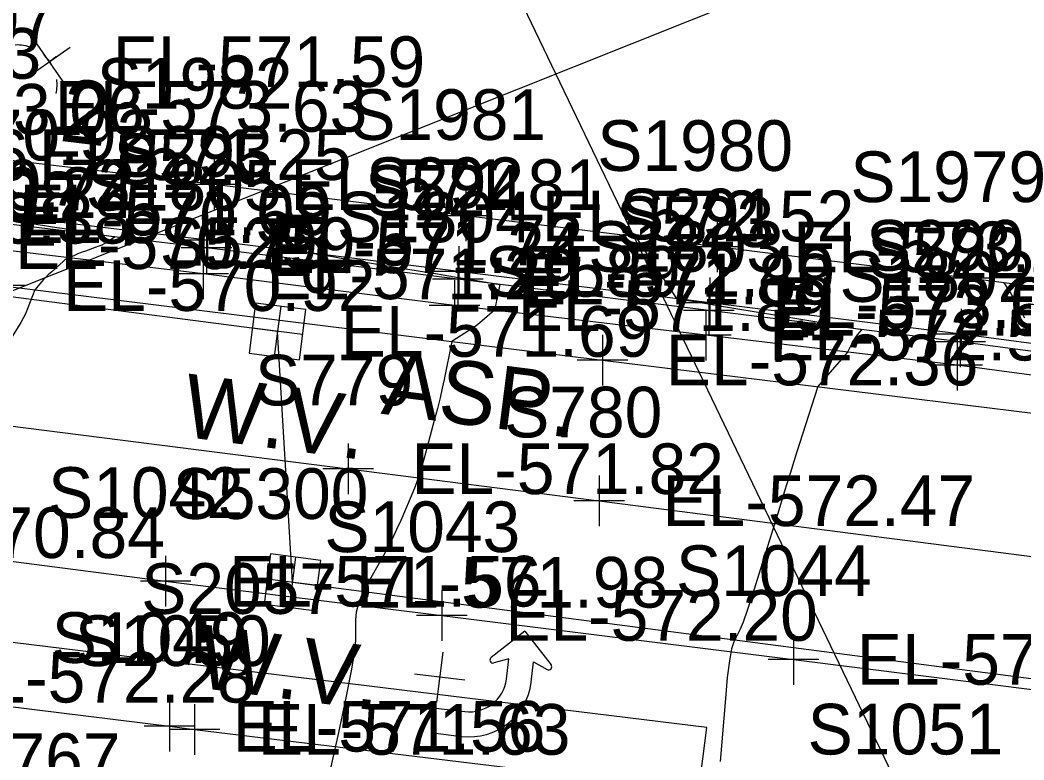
# Model space of a CAD drawing. Extents: x 1724534 to 1727318, y 657156 to 660047.
# Drawn here: x 1725826.2 to 1725905.5, y 658565.7 to 658624.1 of the extents above; entities that cross this region are included whole.
import ezdxf

# ---------------------------------------------------------------- set-up
doc = ezdxf.new("R2010")
doc.units = 0
for name, color, linetype in [('SURVEY - CENTERLINE - Preliminary Text', 7, 'Continuous'), ('SURVEY - CONTOURS - Intermediate with optional Text', 7, 'Continuous'), ('SURVEY - DRAINAGE - Area Shapes', 7, 'Continuous'), ('SURVEY - DRAINAGE - Storm Sewer', 7, 'Continuous'), ('SURVEY - DTM - Breaklines', 7, 'Continuous'), ('SURVEY - DTM - Breaklines - Points - Elevations', 7, 'Continuous'), ('SURVEY - DTM - Breaklines - Points - Locators', 7, 'Continuous'), ('SURVEY - DTM - Breaklines - Points - Numbers', 7, 'Continuous'), ('SURVEY - ROADSIDE BARRIERS - Points - Elevations', 7, 'Continuous'), ('SURVEY - ROADSIDE BARRIERS - Points - Numbers', 7, 'Continuous'), ('SURVEY - TRAFFIC CONTROL - Pavement Marking - Points - Elevations', 7, 'Continuous'), ('SURVEY - TRAFFIC CONTROL - Pavement Marking - Points - Locators', 7, 'Continuous'), ('SURVEY - TRAFFIC CONTROL - Pavement Marking - Points - Numbers', 7, 'Continuous'), ('SURVEY - TRAFFIC CONTROL - Pavement Marking with Text', 7, 'Continuous'), ('SURVEY - TRANSPORTATION - Features', 7, 'Continuous'), ('SURVEY - TRANSPORTATION - Features - Points - Elevations', 7, 'Continuous'), ('SURVEY - TRANSPORTATION - Features - Points - Locators', 7, 'Continuous'), ('SURVEY - TRANSPORTATION - Features - Points - Numbers', 7, 'Continuous'), ('SURVEY - TRANSPORTATION - Features Text', 7, 'Continuous'), ('SURVEY - TRANSPORTATION - Roads', 7, 'Continuous'), ('SURVEY - TRANSPORTATION - Roads - Points - Elevations', 7, 'Continuous'), ('SURVEY - TRANSPORTATION - Roads - Points - Locators', 7, 'Continuous'), ('SURVEY - TRANSPORTATION - Roads - Points - Numbers', 7, 'Continuous'), ('SURVEY - UTILITIES - Poles and Miscellaneous - Points - Elevations', 7, 'Continuous'), ('SURVEY - UTILITIES - Poles and Miscellaneous - Points - Locators', 7, 'Continuous'), ('SURVEY - UTILITIES - Poles and Miscellaneous with Text', 7, 'Continuous'), ('SURVEY - UTILITIES - Water - Points - Elevations', 7, 'Continuous'), ('SURVEY - UTILITIES - Water - Points - Locators', 7, 'Continuous'), ('SURVEY - UTILITIES - Water - Points - Numbers', 7, 'Continuous'), ('SURVEY - UTILITIES - Water with Text', 7, 'Continuous')]:
    doc.layers.add(name, color=color, linetype=linetype)

msp = doc.modelspace()

# ---------------------------------------------------------------- linework, layer by layer
at = {"layer": 'SURVEY - CENTERLINE - Preliminary Text'}
msp.add_line((1725772.853, 658581.708), (1725925.415, 658642.543), dxfattribs=at)
at = {"layer": 'SURVEY - CONTOURS - Intermediate with optional Text'}
for points in [[(1725846.883, 658610.445), (1725847.229, 658609.737), (1725847.817, 658608.493), (1725849.121, 658605.72), (1725851.058, 658605.397), (1725851.572, 658605.312), (1725852.077, 658605.228), (1725856.35, 658604.519), (1725858.166, 658604.22), (1725859.028, 658604.079), (1725859.647, 658603.976), (1725860.528, 658603.83), (1725860.808, 658603.784), (1725860.87, 658603.774), (1725861.796, 658603.619), (1725864.101, 658603.234), (1725863.926, 658602.302), (1725863.891, 658602.114), (1725863.857, 658601.949), (1725863.827, 658601.807), (1725863.8, 658601.687), (1725863.678, 658601.184), (1725862.72, 658600.344), (1725862.503, 658600.163), (1725862.262, 658599.98), (1725861.998, 658599.795), (1725861.709, 658599.609), (1725860.307, 658598.732), (1725859.707, 658595.722), (1725859.562, 658595.036), (1725859.385, 658594.269), (1725859.175, 658593.421), (1725858.933, 658592.491), (1725858.245, 658589.903), (1725857.98, 658588.963), (1725857.702, 658588.086), (1725857.412, 658587.272), (1725857.108, 658586.519), (1725856.281, 658584.597), (1725855.954, 658583.868), (1725855.595, 658583.124), (1725855.203, 658582.364), (1725854.778, 658581.589), (1725853.601, 658579.503), (1725853.215, 658578.743), (1725852.939, 658578.03), (1725852.773, 658577.363), (1725852.717, 658576.741), (1725852.714, 658575.145), (1725852.629, 658574.241), (1725852.375, 658572.723), (1725851.952, 658570.593), (1725851.361, 658567.85), (1725849.559, 658559.717)], [(1725826.087, 658608.215), (1725826.634, 658608.127), (1725827.177, 658608.039), (1725828.622, 658607.807), (1725829.121, 658607.726), (1725829.534, 658607.66), (1725829.861, 658607.607), (1725830.103, 658607.568), (1725830.858, 658607.447), (1725831.134, 658607.403), (1725831.462, 658607.35), (1725831.841, 658607.289), (1725833.73, 658606.984), (1725833.032, 658606.535), (1725832.865, 658606.438), (1725832.663, 658606.339), (1725832.427, 658606.238), (1725832.156, 658606.135), (1725831.387, 658605.859), (1725831.127, 658605.764), (1725830.923, 658605.689), (1725830.776, 658605.632), (1725830.685, 658605.594), (1725830.518, 658605.518), (1725830.456, 658605.491), (1725830.393, 658605.466), (1725830.33, 658605.445), (1725830.267, 658605.427), (1725829.971, 658605.349), (1725828.715, 658604.232), (1725828.465, 658604.005), (1725828.252, 658603.801), (1725828.076, 658603.622), (1725827.938, 658603.466), (1725827.378, 658602.797), (1725826.642, 658600.898), (1725826.282, 658600.218), (1725825.518, 658598.99)], [(1725874.865, 658606.982), (1725875.917, 658605.357), (1725876.397, 658604.627), (1725878.066, 658602.116), (1725880.271, 658601.747), (1725880.867, 658601.648), (1725881.631, 658601.52), (1725886.772, 658600.663), (1725888.832, 658600.319), (1725892.705, 658599.672), (1725892.341, 658599.253), (1725892.261, 658599.152), (1725892.178, 658599.029), (1725892.091, 658598.884), (1725892.001, 658598.717), (1725891.571, 658597.887), (1725890.939, 658597.147), (1725890.358, 658596.477), (1725889.218, 658595.164), (1725887.782, 658590.658), (1725887.444, 658589.589), (1725887.043, 658588.312), (1725886.58, 658586.829), (1725886.056, 658585.138), (1725884.574, 658580.353), (1725884.064, 658578.736), (1725883.647, 658577.474), (1725883.323, 658576.566), (1725883.092, 658576.013), (1725882.598, 658575.01), (1725882.417, 658574.448), (1725882.244, 658573.513), (1725882.078, 658572.206), (1725881.921, 658570.526), (1725881.513, 658565.549)], [(1725903.921, 658603.36), (1725904.459, 658602.513), (1725904.579, 658602.319), (1725904.708, 658602.102), (1725904.846, 658601.861), (1725904.993, 658601.596), (1725905.542, 658600.595)]]:
    msp.add_lwpolyline(points, dxfattribs=at)
at = {"layer": 'SURVEY - DRAINAGE - Area Shapes'}
msp.add_lwpolyline([(1725876.527, 658537.521), (1725880.453, 658568.253), (1725462.782, 658619.36), (1725459.014, 658588.567)], close=True, dxfattribs=at)
at = {"layer": 'SURVEY - DRAINAGE - Storm Sewer'}
msp.add_line((1725899.095, 658556.269), (1725845.926, 658666.932), dxfattribs=at)
at = {"layer": 'SURVEY - DTM - Breaklines'}
msp.add_lwpolyline([(1725923.442, 658596.261), (1725920.349, 658596.664), (1725900.537, 658599.315), (1725880.703, 658601.788), (1725860.867, 658604.256), (1725841.017, 658606.73), (1725821.164, 658609.108), (1725805.637, 658611.084), (1725785.8, 658613.524), (1725762.697, 658616.458), (1725748.853, 658618.143), (1725745.613, 658618.535), (1725725.762, 658620.955), (1725705.909, 658623.419), (1725686.061, 658625.875)], dxfattribs=at)
at = {"layer": 'SURVEY - DTM - Breaklines - Points - Locators'}
for p, q in [((1725841.017, 658608.73), (1725841.017, 658604.73)), ((1725843.017, 658606.73), (1725839.017, 658606.73)), ((1725860.867, 658606.256), (1725860.867, 658602.256)), ((1725862.867, 658604.256), (1725858.867, 658604.256)), ((1725880.703, 658603.788), (1725880.703, 658599.788)), ((1725882.703, 658601.788), (1725878.703, 658601.788)), ((1725900.537, 658601.315), (1725900.537, 658597.315)), ((1725902.537, 658599.315), (1725898.537, 658599.315))]:
    msp.add_line(p, q, dxfattribs=at)
at = {"layer": 'SURVEY - TRAFFIC CONTROL - Pavement Marking - Points - Locators'}
for p, q in [((1725852.127, 658590.674), (1725852.127, 658586.674)), ((1725854.127, 658588.674), (1725850.127, 658588.674)), ((1725871.961, 658588.151), (1725871.961, 658584.151)), ((1725873.961, 658586.151), (1725869.961, 658586.151)), ((1725837.716, 658581.798), (1725837.716, 658577.798)), ((1725839.716, 658579.798), (1725835.716, 658579.798)), ((1725859.541, 658579.092), (1725859.541, 658575.092)), ((1725861.541, 658577.092), (1725857.541, 658577.092)), ((1725887.31, 658575.624), (1725887.31, 658571.624)), ((1725859.603, 658574.204), (1725859.117, 658570.234)), ((1725889.31, 658573.624), (1725885.31, 658573.624)), ((1725861.345, 658571.976), (1725857.375, 658572.462)), ((1725838.021, 658570.345), (1725838.021, 658566.345)), ((1725840.005, 658570.1), (1725840.005, 658566.1)), ((1725840.021, 658568.345), (1725836.021, 658568.345)), ((1725842.005, 658568.1), (1725838.005, 658568.1))]:
    msp.add_line(p, q, dxfattribs=at)
at = {"layer": 'SURVEY - TRAFFIC CONTROL - Pavement Marking with Text'}
for p, q in [((1725866.084, 658575.858), (1725863.423, 658573.777)), ((1725866.084, 658575.858), (1725868.164, 658573.197)), ((1725864.825, 658573.675), (1725863.641, 658573.347)), ((1725864.629, 658572.07), (1725864.825, 658573.675)), ((1725866.582, 658571.831), (1725866.779, 658573.437)), ((1725866.779, 658573.437), (1725867.849, 658572.832)), ((1725859.061, 658569.777), (1725858.822, 658567.824)), ((1725859.061, 658569.777), (1725861.34, 658569.498)), ((1725858.822, 658567.824), (1725861.101, 658567.545))]:
    msp.add_line(p, q, dxfattribs=at)
for points in [[(1725469.93, 658636.195), (1725476.311, 658635.371), (1725478.295, 658635.122), (1725516.011, 658630.481), (1725599.369, 658620.164), (1725678.757, 658610.338), (1725738.298, 658602.97), (1725780.716, 658597.719), (1725790.639, 658596.491), (1725852.127, 658588.674), (1725871.961, 658586.151), (1725916.153, 658580.463)], [(1725691.276, 658598.614), (1725717.028, 658595.036), (1725719.009, 658594.766), (1725742.941, 658591.917), (1725766.76, 658588.985), (1725807.969, 658583.629), (1725837.716, 658579.798), (1725859.541, 658577.092), (1725887.31, 658573.624), (1725917.054, 658569.88)], [(1725753.893, 658578.677), (1725768.555, 658576.886), (1725792.375, 658573.977), (1725838.021, 658568.345), (1725840.005, 658568.1), (1725897.548, 658561.116), (1725916.187, 658558.855)]]:
    msp.add_lwpolyline(points, dxfattribs=at)
for centre, radius, start, end in [((1725863.575, 658573.583), 0.246, 128.02638, 285.51954), ((1725867.97, 658573.046), 0.246, 240.57811, 38.02638), ((1725861.699, 658572.429), 4.92, 263.02638, 353.02638), ((1725861.699, 658572.429), 2.952, 263.02638, 353.02638)]:
    msp.add_arc(centre, radius, start, end, dxfattribs=at)
at = {"layer": 'SURVEY - TRANSPORTATION - Features'}
for points in [[(1725923.364, 658595.652), (1725920.271, 658596.054), (1725900.459, 658598.705), (1725880.625, 658601.178), (1725860.79, 658603.646), (1725840.941, 658606.12), (1725821.088, 658608.498), (1725805.562, 658610.474), (1725785.723, 658612.914), (1725762.62, 658615.849), (1725748.776, 658617.533), (1725745.535, 658617.925), (1725725.684, 658620.345), (1725705.833, 658622.809), (1725685.985, 658625.265)], [(1725924.124, 658601.632), (1725920.917, 658601.133), (1725901.098, 658603.73), (1725881.263, 658606.193), (1725861.425, 658608.639), (1725841.56, 658611.106), (1725821.706, 658613.473), (1725806.126, 658615.02), (1725786.298, 658617.46), (1725763.169, 658620.191), (1725751.211, 658621.652), (1725751.19, 658622.534), (1725749.441, 658623.208)], [(1725923.129, 658593.802), (1725920.036, 658594.204), (1725900.224, 658596.854), (1725880.377, 658599.224), (1725860.524, 658601.554), (1725840.686, 658604.065), (1725820.833, 658606.443), (1725805.311, 658608.457), (1725785.478, 658610.975), (1725762.374, 658613.908), (1725762.62, 658615.849)]]:
    msp.add_lwpolyline(points, dxfattribs=at)
at = {"layer": 'SURVEY - TRANSPORTATION - Features - Points - Locators'}
for p, q in [((1725841.56, 658613.106), (1725841.56, 658609.106)), ((1725843.56, 658611.106), (1725839.56, 658611.106)), ((1725861.425, 658610.639), (1725861.425, 658606.639)), ((1725840.941, 658608.12), (1725840.941, 658604.12)), ((1725863.425, 658608.639), (1725859.425, 658608.639)), ((1725881.263, 658608.193), (1725881.263, 658604.193)), ((1725842.941, 658606.12), (1725838.941, 658606.12)), ((1725840.686, 658606.065), (1725840.686, 658602.065)), ((1725883.263, 658606.193), (1725879.263, 658606.193)), ((1725901.098, 658605.73), (1725901.098, 658601.73)), ((1725860.79, 658605.646), (1725860.79, 658601.646)), ((1725842.686, 658604.065), (1725838.686, 658604.065)), ((1725862.79, 658603.646), (1725858.79, 658603.646)), ((1725860.524, 658603.554), (1725860.524, 658599.554)), ((1725903.098, 658603.73), (1725899.098, 658603.73)), ((1725880.625, 658603.178), (1725880.625, 658599.178)), ((1725862.524, 658601.554), (1725858.524, 658601.554)), ((1725882.625, 658601.178), (1725878.625, 658601.178)), ((1725880.377, 658601.224), (1725880.377, 658597.224)), ((1725900.459, 658600.705), (1725900.459, 658596.705)), ((1725882.377, 658599.224), (1725878.377, 658599.224)), ((1725902.459, 658598.705), (1725898.459, 658598.705)), ((1725900.224, 658598.854), (1725900.224, 658594.854)), ((1725902.224, 658596.854), (1725898.224, 658596.854))]:
    msp.add_line(p, q, dxfattribs=at)
at = {"layer": 'SURVEY - TRANSPORTATION - Roads'}
msp.add_lwpolyline([(1725603.861, 658630.44), (1725726.921, 658615.268), (1725763.101, 658610.806), (1725790.88, 658607.344), (1725824.612, 658603.138), (1725872.227, 658597.261), (1725926.076, 658590.615)], dxfattribs=at)
at = {"layer": 'SURVEY - TRANSPORTATION - Roads - Points - Locators'}
for p, q in [((1725826.612, 658603.138), (1725822.612, 658603.138)), ((1725872.227, 658599.261), (1725872.227, 658595.261)), ((1725874.227, 658597.261), (1725870.227, 658597.261))]:
    msp.add_line(p, q, dxfattribs=at)
at = {"layer": 'SURVEY - UTILITIES - Poles and Miscellaneous - Points - Locators'}
for p, q in [((1725829.685, 658619.181), (1725827.381, 658622.451)), ((1725826.898, 658619.664), (1725830.168, 658621.968))]:
    msp.add_line(p, q, dxfattribs=at)
at = {"layer": 'SURVEY - UTILITIES - Poles and Miscellaneous with Text'}
msp.add_line((1725829.105, 658621.219), (1725828.533, 658620.816), dxfattribs=at)
for start, end in [(68.73872, 93.50876), (22.6969, 49.21222), (347.05385, 7.39636), (305.17598, 319.79685)]:
    msp.add_arc((1725826.014, 658619.01), 3.125, start, end, dxfattribs=at)
at = {"layer": 'SURVEY - UTILITIES - Water - Points - Locators'}
for p, q in [((1725846.804, 658601.504), (1725846.292, 658597.536)), ((1725848.532, 658599.264), (1725844.564, 658599.776)), ((1725847.98, 658581.696), (1725847.468, 658577.728)), ((1725849.708, 658579.456), (1725845.74, 658579.968))]:
    msp.add_line(p, q, dxfattribs=at)
at = {"layer": 'SURVEY - UTILITIES - Water with Text'}
for p, q in [((1725846.548, 658599.52), (1725846.548, 658599.52)), ((1725847.724, 658579.712), (1725847.724, 658579.712))]:
    msp.add_line(p, q, dxfattribs=at)
for points in [[(1725847.724, 658579.712), (1725846.548, 658599.52), (1725380.522, 658660.104)], [(1725844.82, 658601.759), (1725844.309, 658597.792), (1725848.276, 658597.281), (1725848.787, 658601.248), (1725844.82, 658601.759)], [(1725845.996, 658581.951), (1725845.485, 658577.984), (1725849.452, 658577.473), (1725849.963, 658581.44), (1725845.996, 658581.951)], [(1725847.724, 658579.712), (1725982.184, 658562.183), (1725988.335, 658559.963), (1726011.571, 658556.88)]]:
    msp.add_lwpolyline(points, dxfattribs=at)

# ---------------------------------------------------------------- texts
at = {"layer": 'SURVEY - DTM - Breaklines - Points - Elevations'}
for s, p in [('EL-570.72', (1725810.637, 658609.084)), ('EL-571.09', (1725826.164, 658607.108)), ('EL-571.72', (1725846.017, 658604.73)), ('EL-572.40', (1725865.867, 658602.256)), ('EL-573.09', (1725885.703, 658599.788))]:
    msp.add_text(s, height=4, dxfattribs=at).set_placement(p)
at = {"layer": 'SURVEY - DTM - Breaklines - Points - Numbers'}
for s, p in [('S293', (1725833.681, 658611.73)), ('S292', (1725853.531, 658609.256)), ('S291', (1725873.525, 658606.788)), ('S290', (1725893.028, 658604.315))]:
    msp.add_text(s, height=4, dxfattribs=at).set_placement(p)
at = {"layer": 'SURVEY - ROADSIDE BARRIERS - Points - Elevations'}
for s, p in [('EL-573.63', (1725828.955, 658615.289)), ('EL-573.06', (1725811.38, 658615.061))]:
    msp.add_text(s, height=4, dxfattribs=at).set_placement(p)
at = {"layer": 'SURVEY - ROADSIDE BARRIERS - Points - Numbers'}
msp.add_text('S707', height=4, dxfattribs=at).set_placement((1725816.619, 658622.289))
at = {"layer": 'SURVEY - TRAFFIC CONTROL - Pavement Marking - Points - Elevations'}
for s, p in [('EL-571.82', (1725857.127, 658586.674)), ('EL-572.47', (1725876.961, 658584.151)), ('EL-570.84', (1725812.969, 658581.629)), ('EL-571.56', (1725842.716, 658577.798)), ('EL-572.20', (1725864.541, 658575.092)), ('EL-573.18', (1725892.31, 658571.624)), ('EL-572.28', (1725820.075, 658570.219)), ('EL-571.56', (1725843.021, 658566.345)), ('EL-571.63', (1725845.005, 658566.1))]:
    msp.add_text(s, height=4, dxfattribs=at).set_placement(p)
at = {"layer": 'SURVEY - TRAFFIC CONTROL - Pavement Marking - Points - Numbers'}
for s, p in [('S779', (1725844.775, 658593.674)), ('S780', (1725864.452, 658591.151)), ('S1042', (1725828.428, 658584.798)), ('S1043', (1725850.253, 658582.092)), ('S1044', (1725878.022, 658578.624)), ('S2057', (1725835.784, 658577.219)), ('S1049', (1725828.718, 658573.345)), ('S1050', (1725830.544, 658573.1)), ('S1051', (1725888.418, 658566.116)), ('S767', (1725821.657, 658563.789))]:
    msp.add_text(s, height=4, dxfattribs=at).set_placement(p)
at = {"layer": 'SURVEY - TRANSPORTATION - Features - Points - Elevations'}
for s, p in [('EL-570.92', (1725812.126, 658613.02)), ('EL-571.25', (1725827.706, 658611.473)), ('EL-571.81', (1725847.56, 658609.106)), ('EL-570.24', (1725810.562, 658608.474)), ('EL-570.38', (1725810.311, 658606.457)), ('EL-570.58', (1725826.088, 658606.498)), ('EL-572.52', (1725867.425, 658606.639)), ('EL-570.75', (1725825.833, 658604.443)), ('EL-571.24', (1725845.941, 658604.12)), ('EL-573.23', (1725887.263, 658604.193)), ('EL-571.29', (1725845.686, 658602.065)), ('EL-571.88', (1725865.79, 658601.646)), ('EL-571.89', (1725865.524, 658599.554)), ('EL-572.58', (1725885.625, 658599.178)), ('EL-572.58', (1725885.377, 658597.224))]:
    msp.add_text(s, height=4, dxfattribs=at).set_placement(p)
at = {"layer": 'SURVEY - TRANSPORTATION - Features - Points - Numbers'}
for s, p in [('S1983', (1725812.418, 658619.473)), ('S1982', (1725832.272, 658617.106)), ('S1981', (1725852.295, 658614.639)), ('S1980', (1725871.802, 658612.193)), ('S1806', (1725811.435, 658611.443)), ('S525', (1725833.605, 658611.12)), ('S1979', (1725891.795, 658609.73)), ('S1805', (1725831.398, 658609.065)), ('S524', (1725853.454, 658608.646)), ('S1804', (1725851.236, 658606.554)), ('S523', (1725873.289, 658606.178)), ('S1803', (1725871.089, 658604.224)), ('S522', (1725893.123, 658603.705)), ('S1802', (1725890.936, 658601.854))]:
    msp.add_text(s, height=4, dxfattribs=at).set_placement(p)
at = {"layer": 'SURVEY - TRANSPORTATION - Features Text'}
msp.add_text('ASP.', height=5, rotation=352.78613, dxfattribs=at).set_placement((1725854.671, 658593.024))
at = {"layer": 'SURVEY - TRANSPORTATION - Roads - Points - Elevations'}
for s, p in [('EL-570.92', (1725829.612, 658601.138)), ('EL-572.36', (1725877.227, 658595.261))]:
    msp.add_text(s, height=4, dxfattribs=at).set_placement(p)
at = {"layer": 'SURVEY - TRANSPORTATION - Roads - Points - Numbers'}
for s, p in [('S1588', (1725815.277, 658608.138)), ('S1589', (1725862.924, 658602.261))]:
    msp.add_text(s, height=4, dxfattribs=at).set_placement(p)
at = {"layer": 'SURVEY - UTILITIES - Poles and Miscellaneous - Points - Elevations'}
msp.add_text('EL-571.59', height=4, dxfattribs=at).set_placement((1725833.533, 658618.816))
at = {"layer": 'SURVEY - UTILITIES - Poles and Miscellaneous with Text'}
msp.add_text('2', height=5, rotation=353.02638, dxfattribs=at).set_placement((1725829.247, 658614.582))
at = {"layer": 'SURVEY - UTILITIES - Water - Points - Elevations'}
for s, p in [('EL-571.69', (1725851.548, 658597.52)), ('EL-571.98', (1725852.724, 658577.712))]:
    msp.add_text(s, height=4, dxfattribs=at).set_placement(p)
at = {"layer": 'SURVEY - UTILITIES - Water - Points - Numbers'}
for s, p in [('S5299', (1725837.245, 658604.52)), ('S5300', (1725838.263, 658584.712))]:
    msp.add_text(s, height=4, dxfattribs=at).set_placement(p)
at = {"layer": 'SURVEY - UTILITIES - Water with Text'}
for p in [(1725838.876, 658591.233), (1725840.052, 658571.425)]:
    msp.add_text('W.V.', height=5.0001, rotation=352.65747, dxfattribs=at).set_placement(p)

doc.saveas('drawing.dxf')
